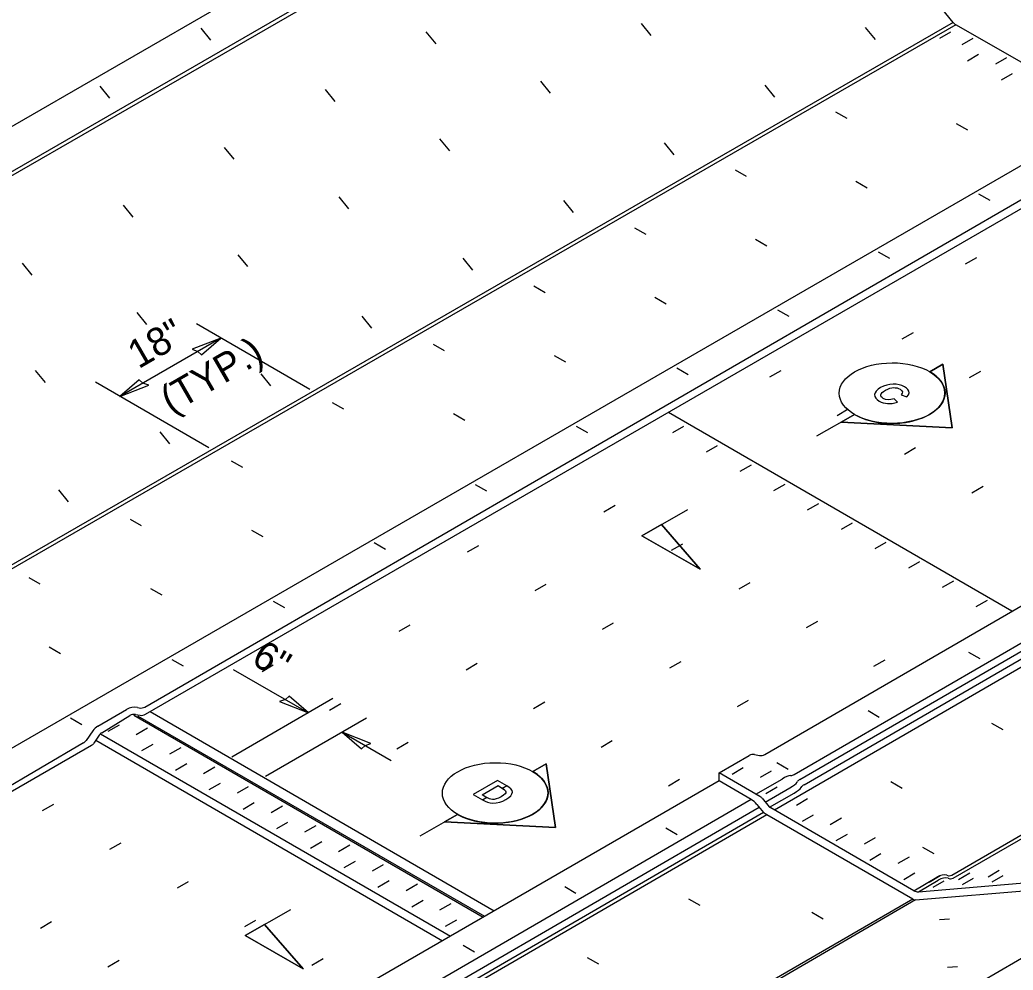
# Model space of a CAD drawing. Extents: x 99862 to 103151, y 100000 to 102076.
# Drawn here: x 101674 to 102236, y 101034 to 101572 of the extents above; entities that cross this region are included whole.
import ezdxf

# ---------------------------------------------------------------- set-up
doc = ezdxf.new("R2010")
doc.units = 0
for name, color, linetype in [('Level 15', 7, 'Continuous'), ('Level 20', 7, 'Continuous'), ('Level 25', 7, 'Continuous'), ('Level 32', 7, 'Continuous'), ('Level 33', 7, 'Continuous'), ('Level 34', 7, 'Continuous'), ('Level 36', 7, 'Continuous'), ('Level 8', 7, 'Continuous'), ('Level 9', 7, 'Continuous')]:
    doc.layers.add(name, color=color, linetype=linetype)

msp = doc.modelspace()

# ---------------------------------------------------------------- linework, layer by layer
at = {"layer": 'Level 15'}
for p, q in [((101838.17, 101362.77), (101774.1, 101399.79)), ((101787.95, 101391.78), (101730.82, 101358.81)), ((101781.04, 101329.8), (101716.96, 101366.81)), ((101794.8, 101204.35), (101837.43, 101179.92)), ((101851.27, 101187.94), (101794.1, 101154.81)), ((101870.37, 101176.89), (101813.17, 101143.79)), ((101856.52, 101168.88), (101884.29, 101152.97))]:
    msp.add_line(p, q, dxfattribs=at)
for points in [[(101787.95, 101391.78), (101771.66, 101385.46), (101774.96, 101384.28), (101777, 101382.38)], [(101730.82, 101358.81), (101747.11, 101365.13), (101743.81, 101366.31), (101741.77, 101368.22)], [(101837.43, 101179.92), (101826.48, 101189.32), (101824.44, 101187.41), (101821.14, 101186.24)], [(101856.52, 101168.88), (101867.47, 101159.47), (101869.51, 101161.38), (101872.81, 101162.56)]]:
    msp.add_lwpolyline(points, close=True, dxfattribs=at)
at = {"layer": 'Level 20'}
for p, q in [((102125.06, 101336.45), (102146.33, 101348.57)), ((102026.08, 101280.03), (102051.93, 101294.77)), ((101900.57, 101110.32), (101921.83, 101122.44)), ((101801.58, 101053.89), (101827.44, 101068.63))]:
    msp.add_line(p, q, dxfattribs=at)
at = {"layer": 'Level 25'}
for p, q in [((102188.81, 101372.79), (102196.32, 101377.07)), ((102196.32, 101377.07), (102188.81, 101372.79)), ((102196.32, 101377.07), (102201.57, 101341.12)), ((102201.57, 101341.12), (102196.32, 101377.07)), ((102138.82, 101344.29), (102146.32, 101348.57)), ((102146.32, 101348.57), (102138.82, 101344.29)), ((102201.57, 101341.12), (102138.82, 101344.29)), ((102138.82, 101344.29), (102201.57, 101341.12)), ((101964.32, 101146.65), (101971.82, 101150.93)), ((101971.82, 101150.93), (101964.32, 101146.65)), ((101971.82, 101150.93), (101977.08, 101114.98)), ((101977.08, 101114.98), (101971.82, 101150.93)), ((101947.15, 101137.18), (101949.59, 101138.6)), ((101949.59, 101138.6), (101947.15, 101137.18)), ((101947.15, 101137.18), (101948.38, 101136.39)), ((101935.84, 101130.59), (101938.25, 101131.99)), ((101938.25, 101131.99), (101935.84, 101130.59)), ((101914.32, 101118.16), (101921.83, 101122.44)), ((101921.83, 101122.44), (101914.32, 101118.16)), ((101977.08, 101114.98), (101914.32, 101118.16)), ((101914.32, 101118.16), (101977.08, 101114.98))]:
    msp.add_line(p, q, dxfattribs=at)
for points in [[(102168.67, 101357.52), (102166.87, 101357.04), (102165.26, 101356.92), (102163.82, 101357.14), (102162.59, 101357.65), (102161.92, 101358.11), (102161.46, 101358.61), (102161.2, 101359.14), (102161.16, 101359.71), (102161.37, 101360.32), (102161.9, 101360.96), (102162.73, 101361.65), (102163.87, 101362.36), (102165.06, 101362.97), (102166.21, 101363.41), (102167.31, 101363.68), (102168.37, 101363.79), (102169.38, 101363.75), (102170.33, 101363.6), (102171.22, 101363.31), (102172.05, 101362.91), (102172.96, 101362.21), (102173.37, 101361.42), (102173.27, 101360.6), (102172.68, 101359.8), (102175.86, 101358.58), (102176.82, 101359.8), (102177.15, 101360.92), (102176.99, 101361.81), (102176.53, 101362.64), (102175.74, 101363.44), (102174.64, 101364.18), (102173.14, 101364.9), (102171.56, 101365.41), (102169.87, 101365.7), (102168.1, 101365.78), (102166.28, 101365.63), (102164.49, 101365.25), (102162.74, 101364.63), (102161.02, 101363.77), (102159.59, 101362.83), (102158.56, 101361.87), (102157.92, 101360.87), (102157.67, 101359.85), (102157.79, 101358.85), (102158.27, 101357.91), (102159.1, 101357.03), (102160.29, 101356.21), (102161.41, 101355.65), (102162.58, 101355.22), (102163.78, 101354.92), (102165.04, 101354.76), (102166.34, 101354.74), (102167.68, 101354.86), (102169.07, 101355.13), (102170.52, 101355.53), (102168.67, 101357.52)], [(102168.67, 101357.52), (102166.87, 101357.04), (102165.26, 101356.92), (102163.82, 101357.14), (102162.59, 101357.65), (102161.92, 101358.11), (102161.46, 101358.61), (102161.2, 101359.14), (102161.16, 101359.71), (102161.37, 101360.32), (102161.9, 101360.96), (102162.73, 101361.65), (102163.87, 101362.36), (102165.06, 101362.97), (102166.21, 101363.41), (102167.31, 101363.68), (102168.37, 101363.79), (102169.38, 101363.75), (102170.33, 101363.6), (102171.22, 101363.31), (102172.05, 101362.91), (102172.96, 101362.21), (102173.37, 101361.42), (102173.27, 101360.6), (102172.68, 101359.8), (102175.86, 101358.58), (102176.82, 101359.8), (102177.15, 101360.92), (102176.99, 101361.81), (102176.53, 101362.64), (102175.74, 101363.44), (102174.64, 101364.18), (102173.14, 101364.9), (102171.56, 101365.41), (102169.87, 101365.7), (102168.1, 101365.78), (102166.28, 101365.63), (102164.49, 101365.25), (102162.74, 101364.63), (102161.02, 101363.77), (102159.59, 101362.83), (102158.56, 101361.87), (102157.92, 101360.87), (102157.67, 101359.85), (102157.79, 101358.85), (102158.27, 101357.91), (102159.1, 101357.03), (102160.29, 101356.21), (102161.41, 101355.65), (102162.58, 101355.22), (102163.78, 101354.92), (102165.04, 101354.76), (102166.34, 101354.74), (102167.68, 101354.86), (102169.07, 101355.13), (102170.52, 101355.53), (102168.67, 101357.52)], [(102037.07, 101286.3), (102058.97, 101261.1), (102026.08, 101280.03), (102037.07, 101286.3)], [(102026.08, 101280.03), (102058.97, 101261.1), (102037.07, 101286.3), (102026.08, 101280.03)], [(101949.03, 101130.81), (101950.71, 101131.9), (101951.86, 101132.95), (101952.52, 101133.97), (101952.78, 101134.99), (101952.6, 101135.99), (101951.96, 101136.93), (101951.05, 101137.68), (101949.59, 101138.6), (101944.46, 101141.55), (101930.57, 101133.63), (101935.84, 101130.59), (101937.31, 101129.83), (101938.62, 101129.33), (101940.21, 101128.96), (101941.7, 101128.83), (101943.64, 101128.95), (101945.64, 101129.37), (101947.32, 101129.96), (101949.03, 101130.81)], [(101949.59, 101138.6), (101944.46, 101141.55), (101930.57, 101133.63), (101935.84, 101130.59)], [(101946.51, 101132.41), (101945, 101131.64), (101943.69, 101131.15), (101942.55, 101130.9), (101941.58, 101130.85), (101940.69, 101130.96), (101939.8, 101131.22), (101937.86, 101132.19), (101935.62, 101133.48), (101944.7, 101138.66), (101946.05, 101137.88), (101948.38, 101136.39), (101948.9, 101135.81), (101949.12, 101135.23), (101949.03, 101134.62), (101948.65, 101133.98), (101947.83, 101133.25), (101946.51, 101132.41)], [(101938.25, 101131.99), (101937.86, 101132.19), (101935.62, 101133.48), (101944.7, 101138.66), (101946.05, 101137.88), (101947.15, 101137.18)], [(101935.84, 101130.59), (101937.31, 101129.83), (101938.62, 101129.33), (101940.21, 101128.96), (101941.7, 101128.83), (101943.64, 101128.95), (101945.64, 101129.37), (101947.32, 101129.96), (101949.03, 101130.81), (101950.71, 101131.9), (101951.86, 101132.95), (101952.52, 101133.97), (101952.78, 101134.99), (101952.6, 101135.99), (101951.96, 101136.93), (101951.05, 101137.68), (101949.59, 101138.6)], [(101948.38, 101136.39), (101948.9, 101135.81), (101949.12, 101135.23), (101949.03, 101134.62), (101948.65, 101133.98), (101947.83, 101133.25), (101946.51, 101132.41), (101945, 101131.64), (101943.69, 101131.15), (101942.55, 101130.9), (101941.58, 101130.85), (101940.69, 101130.96), (101939.8, 101131.22), (101938.25, 101131.99)], [(101812.58, 101060.16), (101834.48, 101034.97), (101801.58, 101053.89), (101812.58, 101060.16)], [(101801.58, 101053.89), (101834.48, 101034.97), (101812.58, 101060.16), (101801.58, 101053.89)]]:
    msp.add_lwpolyline(points, dxfattribs=at)
for centre, major_axis, ratio in [((102167.57, 101360.68), (29.91, 0.12), 0.572685), ((101943.07, 101134.54), (29.9, 0.12), 0.572617)]:
    msp.add_ellipse(centre, major_axis=major_axis, ratio=ratio, dxfattribs=at)
for centre, start_param, end_param in [((102167.57, 101360.68), 3.920114, 7.061799), ((102167.57, 101360.68), 5.490949, 7.061799), ((102167.57, 101360.68), 3.920114, 5.425871), ((102167.57, 101360.68), 5.425871, 5.490949), ((101943.07, 101134.54), 3.920114, 7.061799), ((101943.07, 101134.54), 5.490949, 7.061799), ((101943.07, 101134.54), 3.920114, 5.425871), ((101943.07, 101134.54), 5.425871, 5.490949)]:
    msp.add_ellipse(centre, major_axis=(29.9, 0.12), ratio=0.572617, start_param=start_param, end_param=end_param, dxfattribs=at)
at = {"layer": 'Level 32'}
for p, q in [((102041.13, 101349.86), (102235.24, 101237.61)), ((101738.63, 101178.46), (101936.19, 101064.25)), ((101740.85, 101178.24), (101937.11, 101064.78)), ((101747.83, 101180.52), (101942.57, 101067.95)), ((101719.74, 101168.02), (101917.7, 101053.53)), ((101717.16, 101164.31), (101913.21, 101050.93))]:
    msp.add_line(p, q, dxfattribs=at)
at = {"layer": 'Level 33'}
msp.add_line((102758.7, 101342.08), (101851.56, 100814.75), dxfattribs=at)
at = {"layer": 'Level 34'}
for p, q in [((102202.09, 101570.34), (102080.62, 101721.03)), ((102202.09, 101570.34), (101559.63, 101200.22)), ((102203.67, 101568.94), (101561.64, 101199.06)), ((102285.7, 101521.95), (102203.67, 101568.94)), ((102294.49, 101520.54), (101638.34, 101141.86)), ((101744.83, 101183.13), (102312.53, 101511.76)), ((101745.29, 101179.05), (102312.51, 101506.55)), ((102095.53, 101156.34), (102510.44, 101396.84)), ((102112.22, 101145.05), (102528.55, 101386.46)), ((102115.46, 101142.15), (102531.79, 101383.58)), ((102117.79, 101139.22), (102534.12, 101380.66)), ((102537.36, 101377.78), (102101.11, 101124.77)), ((102201.41, 101088.11), (102619.93, 101330.47)), ((102202.13, 101086.42), (102623.13, 101329.63)), ((101718.39, 101172.39), (101734.57, 101181.77)), ((101720.51, 101168.61), (101736.51, 101178.29)), ((101739.55, 101178.88), (101742.25, 101178.45)), ((101740.67, 101182.84), (101741.74, 101182.65)), ((101715.48, 101169.69), (101711.68, 101164.16)), ((101719.08, 101167.23), (101716.15, 101162.78)), ((101710.25, 101162.82), (101617.95, 101108.61)), ((101714.72, 101161.4), (101638.42, 101117.35)), ((102069.69, 101145.87), (102086.74, 101155.75)), ((102089.79, 101156.29), (102092.48, 101155.8)), ((102069.69, 101141.37), (102069.69, 101145.87)), ((102092.77, 101132.53), (102069.69, 101145.87)), ((102110.05, 101144.35), (102110.64, 101144.4)), ((102069.69, 101141.37), (101595.22, 100867.16)), ((102069.69, 101141.37), (102069.69, 101142.7)), ((102087.81, 101130.9), (102069.69, 101141.37)), ((102090.54, 101133.82), (102105.33, 101142.39)), ((102113.78, 101140.59), (102114.12, 101141.1)), ((102116.11, 101137.66), (102116.45, 101138.16)), ((102095.8, 101129.34), (102109.76, 101137.43)), ((102098.26, 101126.48), (102112.09, 101134.49)), ((102087.81, 101130.9), (101614.01, 100856.17)), ((102091.05, 101128), (102094.82, 101123.51)), ((102093.97, 101131.52), (102098.06, 101126.65)), ((102092.4, 101126.39), (101618.65, 100851.66)), ((102094.82, 101123.51), (101620.99, 100848.7)), ((102096.63, 101122.16), (101622.29, 100847.06)), ((102179.2, 101074.44), (102096.63, 101122.16)), ((102179.86, 101079.25), (102098.88, 101126.06)), ((102198.59, 101087.99), (102199.53, 101087.73)), ((102179.86, 101079.25), (102192.94, 101086.85)), ((102182.5, 101078.67), (102193.66, 101085.15)), ((102182.5, 101078.67), (102251.99, 101084.57)), ((102199.31, 101086.29), (102200.25, 101086.03)), ((102180.8, 101074.01), (102251.38, 101080)), ((102179.2, 101074.44), (101703.3, 100798.93)), ((102180.8, 101074.01), (101705.93, 100798.33))]:
    msp.add_line(p, q, dxfattribs=at)
for centre, radius, start, end in [((101739.09, 101173.98), 9, 79.8578, 120.0973), ((101742.63, 101187.11), 4.55, 258.6519, 298.8692), ((101738.84, 101174.44), 4.5, 80.9424, 121.182), ((101742.96, 101182.9), 4.5, 260.9424, 301.1825), ((101722.9, 101164.6), 9, 120.0973, 145.5529), ((101722.84, 101164.76), 4.5, 121.182, 146.6375), ((101707.97, 101166.7), 4.5, 300.4265, 325.5529), ((101712.39, 101165.25), 4.5, 301.146, 326.6978), ((102089, 101151.86), 4.5, 79.8578, 120.0973), ((102093.27, 101160.23), 4.5, 259.8578, 300.0979), ((102090.52, 101128.63), 4.5, 39.9757, 59.9757), ((102182.11, 101083.15), 4.5, 239.9741, 274.8534)]:
    msp.add_arc(centre, radius, start, end, dxfattribs=at)
for centre, major_axis, ratio, start_param, end_param in [((102203.68, 101572.6), (2.23, -3.87), 0.581242, 4.976324, 5.499412), ((102100.53, 101135.62), (-10.52, -8.46), 0.208603, 3.4445, 4.079793), ((102113.81, 101147.31), (-3.51, -2.82), 0.208612, 0.302892, 0.938106), ((102101.42, 101136.84), (-12.62, -4.8), 0.222016, 2.205636, 2.840929), ((102118.24, 101142.35), (-4.21, -1.6), 0.222025, 5.347324, 5.982538), ((102120.57, 101139.41), (-4.21, -1.6), 0.222068, 5.347338, 5.982553), ((102103.75, 101133.9), (-12.62, -4.8), 0.222058, 2.20565, 2.840943), ((102192.91, 101075.84), (6.76, 11.69), 0.573628, 0.150896, 0.786168), ((102201.42, 101091.78), (2.25, 3.9), 0.573634, 3.292398, 3.382435), ((102201.42, 101091.78), (2.25, 3.9), 0.573634, 3.382435, 3.417928), ((102201.42, 101091.78), (2.25, 3.9), 0.573634, 3.417928, 3.927619), ((102193.63, 101074.14), (6.76, 11.69), 0.573628, 0.150896, 0.786168), ((102202.14, 101090.08), (2.25, 3.9), 0.573634, 3.292398, 3.382435), ((102202.14, 101090.08), (2.25, 3.9), 0.573634, 3.382435, 3.417928), ((102202.14, 101090.08), (2.25, 3.9), 0.573634, 3.417928, 3.927619), ((102179.21, 101078.11), (-2.26, 3.89), 0.578547, 2.351551, 2.874648)]:
    msp.add_ellipse(centre, major_axis=major_axis, ratio=ratio, start_param=start_param, end_param=end_param, dxfattribs=at)
for points, degree in [([(102091.05, 101128), (102090.05, 101129.26), (102088.97, 101130.23), (102087.81, 101130.9)], 3), ([(102096.63, 101122.16), (102096, 101122.53), (102095.4, 101122.97), (102094.82, 101123.51)], 3), ([(102098.88, 101126.06), (102098.62, 101126.21), (102098.34, 101126.4), (102098.06, 101126.65)], 2)]:
    msp.add_open_spline(points, degree=degree, dxfattribs=at)
at = {"layer": 'Level 36'}
for p, q in [((101782.32, 101560.32), (101776.81, 101567.08)), ((101909.59, 101558.28), (101904.08, 101565.04)), ((102031.29, 101562.97), (102025.78, 101569.72)), ((102158.11, 101560.67), (102152.6, 101567.43)), ((102200.61, 101564.84), (102194.31, 101561.21)), ((102213.26, 101561.21), (102206.96, 101557.58)), ((102216.46, 101552.13), (102210.16, 101548.5)), ((102232.27, 101550.32), (102225.97, 101546.68)), ((101974.35, 101530.34), (101968.84, 101537.09)), ((102235.48, 101541.24), (102229.18, 101537.6)), ((101725.18, 101527.58), (101719.67, 101534.34)), ((101725.18, 101527.58), (101719.67, 101534.34)), ((101852.59, 101525.62), (101847.07, 101532.37)), ((102101.24, 101528.08), (102095.72, 101534.83)), ((102135.55, 101519.75), (102141.9, 101516.1)), ((102203.86, 101513.24), (102210.2, 101509.61)), ((101917.34, 101497.67), (101911.83, 101504.43)), ((101795.51, 101492.91), (101790, 101499.67)), ((102044.36, 101495.48), (102038.85, 101502.24)), ((102078.75, 101486.96), (102085.09, 101483.32)), ((102147.11, 101480.49), (102153.46, 101476.85)), ((101860.27, 101464.97), (101854.76, 101471.72)), ((101987.41, 101462.85), (101981.9, 101469.61)), ((102216.5, 101473.37), (102222.84, 101469.73)), ((101738.37, 101460.17), (101732.86, 101466.94)), ((102021.87, 101454.14), (102028.22, 101450.49)), ((102090.3, 101447.7), (102096.65, 101444.07)), ((101803.13, 101432.22), (101797.62, 101438.98)), ((101930.41, 101430.19), (101924.89, 101436.94)), ((102159.69, 101440.59), (102166.04, 101436.95)), ((102215.27, 101437.25), (102208.97, 101433.61)), ((101681.17, 101427.39), (101675.65, 101434.16)), ((101964.93, 101421.28), (101971.28, 101417.63)), ((102033.43, 101414.88), (102039.78, 101411.24)), ((102102.82, 101407.77), (102109.16, 101404.12)), ((101745.99, 101399.48), (101740.48, 101406.24)), ((101873.33, 101397.48), (101867.82, 101404.24)), ((102179.4, 101394.77), (102173.1, 101391.13)), ((101907.93, 101388.38), (101914.28, 101384.72)), ((101976.49, 101382.01), (101982.84, 101378.38)), ((102045.88, 101374.91), (102052.22, 101371.25)), ((101688.66, 101366.63), (101683.14, 101373.39)), ((101816.19, 101364.74), (101810.68, 101371.5)), ((102104.56, 101373.37), (102098.26, 101369.73)), ((102217.53, 101372.92), (102211.23, 101369.29)), ((101850.86, 101355.45), (101857.21, 101351.78)), ((102142.7, 101351.51), (102136.4, 101347.88)), ((101919.49, 101349.11), (101925.84, 101345.47)), ((101988.88, 101342.01), (101995.22, 101338.35)), ((102049.63, 101341.82), (102043.33, 101338.18)), ((101759.06, 101332), (101753.54, 101338.76)), ((102068.7, 101330.89), (102062.4, 101327.25)), ((102180.82, 101329.67), (102174.52, 101326.03)), ((101793.73, 101322.47), (101800.08, 101318.81)), ((102087.77, 101319.96), (102081.47, 101316.33)), ((101931.81, 101309.08), (101938.15, 101305.41)), ((102106.83, 101309.04), (102100.53, 101305.4)), ((102218.97, 101307.81), (102212.67, 101304.17)), ((101701.72, 101299.14), (101696.21, 101305.9)), ((102010.84, 101297.07), (102004.54, 101293.43)), ((102125.89, 101298.12), (102119.59, 101294.48)), ((101736.53, 101289.46), (101742.88, 101285.79)), ((102144.96, 101287.19), (102138.66, 101283.55)), ((101805.29, 101283.2), (101811.63, 101279.56)), ((101874.67, 101276.1), (101881.02, 101272.44)), ((101933.59, 101274.27), (101927.29, 101270.63)), ((102048.97, 101275.22), (102042.67, 101271.58)), ((102164.04, 101276.26), (102157.74, 101272.62)), ((102183.13, 101265.32), (102176.83, 101261.68)), ((101679.27, 101256.41), (101685.61, 101252.74)), ((101971.73, 101252.41), (101965.43, 101248.78)), ((102087.11, 101253.37), (102080.81, 101249.73)), ((102202.19, 101254.4), (102195.89, 101250.76)), ((101748.09, 101250.18), (101754.44, 101246.54)), ((101817.47, 101243.09), (101823.82, 101239.42)), ((102221.26, 101243.47), (102214.96, 101239.83)), ((101894.8, 101229.52), (101888.5, 101225.88)), ((102009.85, 101230.57), (102003.55, 101226.93)), ((102125.27, 101231.5), (102118.97, 101227.86)), ((101690.83, 101217.12), (101697.17, 101213.49)), ((102217.4, 101210.3), (102211.03, 101213.97)), ((101760.21, 101210.04), (101766.56, 101206.37)), ((101817.55, 101206.72), (101811.25, 101203.08)), ((101932.93, 101207.67), (101926.63, 101204.03)), ((102048, 101208.71), (102041.7, 101205.07)), ((102163.41, 101209.64), (102157.11, 101206.01)), ((101855.69, 101184.87), (101849.39, 101181.23)), ((101971.07, 101185.82), (101964.77, 101182.18)), ((102086.15, 101186.85), (102079.85, 101183.21)), ((102160.33, 101177.21), (102153.96, 101180.89)), ((101702.88, 101176.95), (101709.23, 101173.28)), ((101724.19, 101169.48), (101730.55, 101173.15)), ((101724.19, 101169.48), (101730.55, 101173.15)), ((101724.19, 101169.48), (101730.55, 101173.15)), ((102230.32, 101170.22), (102223.94, 101173.87)), ((101740.07, 101167.65), (101746.43, 101171.32)), ((101740.07, 101167.65), (101746.43, 101171.32)), ((101743.24, 101158.47), (101749.6, 101162.14)), ((101743.24, 101158.47), (101749.6, 101162.14)), ((101893.81, 101163.02), (101887.51, 101159.38)), ((102009.23, 101163.95), (102002.93, 101160.31)), ((101759.12, 101156.63), (101765.48, 101160.3)), ((101759.12, 101156.63), (101765.48, 101160.3)), ((101762.29, 101147.45), (101768.65, 101151.12)), ((101762.29, 101147.45), (101768.65, 101151.12)), ((101778.18, 101145.61), (101784.54, 101149.28)), ((101778.18, 101145.61), (101784.54, 101149.28)), ((102108.81, 101147.81), (102102.43, 101151.49)), ((102083.36, 101148.68), (102077.06, 101145.02)), ((102099.22, 101146.85), (102092.92, 101143.2)), ((101781.36, 101136.42), (101787.71, 101140.1)), ((101781.36, 101136.42), (101787.71, 101140.1)), ((101797.25, 101134.59), (101803.6, 101138.26)), ((101797.25, 101134.59), (101803.6, 101138.26)), ((102047.37, 101142.1), (102041.07, 101138.46)), ((102173.25, 101137.14), (102166.88, 101140.79)), ((102102.48, 101137.72), (102096.18, 101134.07)), ((101693.16, 101128.06), (101686.86, 101124.42)), ((101800.43, 101125.4), (101806.78, 101129.07)), ((101800.43, 101125.4), (101806.78, 101129.07)), ((101800.43, 101125.4), (101806.78, 101129.07)), ((101816.32, 101123.56), (101822.68, 101127.24)), ((101816.32, 101123.56), (101822.68, 101127.24)), ((102119.71, 101131.15), (102113.41, 101127.5)), ((102122.98, 101122.02), (102116.68, 101118.36)), ((101819.5, 101114.37), (101825.86, 101118.04)), ((101835.4, 101112.53), (101841.76, 101116.2)), ((102138.85, 101120.19), (102132.55, 101116.53)), ((102138.85, 101120.19), (102132.55, 101116.53)), ((102046, 101110.92), (102039.63, 101114.61)), ((102142.12, 101111.05), (102135.82, 101107.4)), ((101731.29, 101106.21), (101724.99, 101102.57)), ((101838.59, 101103.33), (101844.94, 101107.01)), ((101854.49, 101101.49), (101860.85, 101105.17)), ((102157.99, 101109.22), (102151.69, 101105.57)), ((102161.26, 101100.08), (102154.96, 101096.42)), ((102191.39, 101100.09), (102185.01, 101103.77)), ((101857.68, 101092.29), (101864.04, 101095.97)), ((101873.58, 101090.45), (101879.94, 101094.13)), ((102177.14, 101098.25), (102170.84, 101094.6)), ((102180.42, 101089.11), (102174.12, 101085.45)), ((102194.79, 101087.63), (102188.49, 101083.97)), ((102211.46, 101089.11), (102205.16, 101085.45)), ((102228.13, 101090.6), (102221.83, 101086.94)), ((102230.17, 101087.68), (102223.87, 101084.02)), ((101769.42, 101084.36), (101763.13, 101080.72)), ((101876.78, 101081.25), (101883.13, 101084.93)), ((101892.69, 101079.4), (101899.04, 101083.09)), ((102196.82, 101084.71), (102190.52, 101081.05)), ((102213.49, 101086.2), (102207.19, 101082.54)), ((101988.74, 101077.72), (101982.36, 101081.41)), ((101895.88, 101070.2), (101902.24, 101073.88)), ((101911.8, 101068.36), (101918.15, 101072.04)), ((102058.92, 101070.85), (102052.54, 101074.51)), ((102128.58, 101063.2), (102122.2, 101066.88)), ((101692.17, 101061.56), (101685.87, 101057.92)), ((101807.59, 101062.49), (101801.29, 101058.85)), ((101915, 101059.14), (101921.35, 101062.83)), ((102194.4, 101063), (102199.99, 101063.36)), ((101931.41, 101044.48), (101925.03, 101048.17)), ((101730.32, 101039.7), (101724.02, 101036.06)), ((101845.73, 101040.64), (101839.43, 101037)), ((102001.65, 101037.66), (101995.28, 101041.31)), ((102198.88, 101035.92), (102204.47, 101036.3))]:
    msp.add_line(p, q, dxfattribs=at)
at = {"layer": 'Level 8'}
msp.add_line((102067.71, 101741.29), (101577.26, 101458.13), dxfattribs=at)
at = {"layer": 'Level 9'}
for p, q in [((101564.17, 101425.05), (102081.74, 101723.87)), ((101564.17, 101422.85), (102081.74, 101721.67))]:
    msp.add_line(p, q, dxfattribs=at)

# ---------------------------------------------------------------- texts
at = {"layer": 'Level 20'}
for s, rotation, p in [('18"', 29.9987, (101741.33, 101374.11)), ('(TYP.)', 29.9987, (101759.77, 101348.58)), ('6"', 330.0271, (101804.44, 101207.91))]:
    msp.add_text(s, height=16, rotation=rotation, dxfattribs=at).set_placement(p)

doc.saveas('drawing.dxf')
